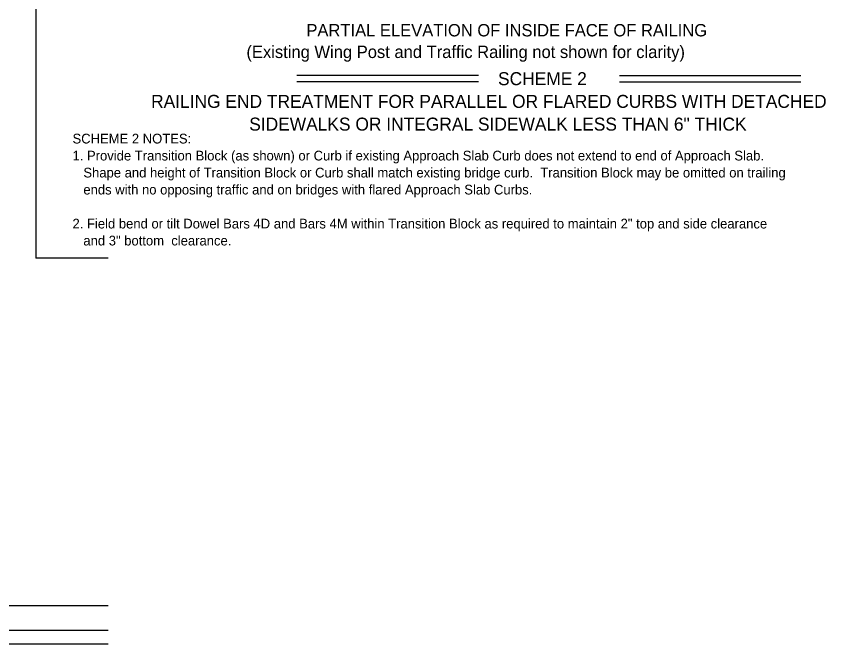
# Model space of a CAD drawing. Extents: x 21526.6 to 21598.7, y 56118.1 to 56155.9.
# Drawn here: x 21545.31 to 21562.06, y 56119.33 to 56132.33 of the extents above; entities that cross this region are included whole.
import ezdxf

# ---------------------------------------------------------------- set-up
doc = ezdxf.new("R2010")
doc.units = 0
doc.layers.add('Border', color=7, linetype='Continuous')
doc.layers.add('PlotBorder_dp', color=7, linetype='Continuous')

msp = doc.modelspace()

# ---------------------------------------------------------------- linework, layer by layer
at = {"layer": 'Border'}
for p, q in [((21547.212, 56120.12), (21526.6, 56120.12)), ((21547.212, 56119.605), (21526.6, 56119.605)), ((21526.6, 56119.332), (21547.212, 56119.332))]:
    msp.add_line(p, q, dxfattribs=at)
at = {"layer": 'PlotBorder_dp'}
for p, q in [((21545.716, 56153.256), (21545.716, 56127.317)), ((21554.877, 56131.105), (21551.118, 56131.105)), ((21557.792, 56131.105), (21561.551, 56131.105)), ((21554.877, 56130.972), (21551.118, 56130.972)), ((21557.792, 56130.972), (21561.551, 56130.972)), ((21547.212, 56127.317), (21545.716, 56127.317))]:
    msp.add_line(p, q, dxfattribs=at)

# ---------------------------------------------------------------- texts
for s, height, p in [('PARTIAL ELEVATION OF INSIDE FACE OF RAILING', 0.256, (21551.315, 56131.912)), ('(Existing Wing Post and Traffic Railing not shown for clarity)', 0.256, (21550.074, 56131.464)), ('SCHEME 2', 0.2688, (21555.281, 56130.902)), ('RAILING END TREATMENT FOR PARALLEL OR FLARED CURBS WITH DETACHED', 0.2688, (21548.101, 56130.432)), ('SIDEWALKS OR INTEGRAL SIDEWALK LESS THAN 6" THICK', 0.2688, (21550.132, 56129.961)), ('SCHEME 2 NOTES:', 0.2016, (21546.475, 56129.694)), ('1. Provide Transition Block (as shown) or Curb if existing Approach Slab Curb does not extend to end of Approach Slab.  ', 0.2016, (21546.475, 56129.342)), ('   Shape and height of Transition Block or Curb shall match existing bridge curb.  Transition Block may be omitted on trailing ', 0.2016, (21546.475, 56128.99)), ('   ends with no opposing traffic and on bridges with flared Approach Slab Curbs.', 0.2016, (21546.475, 56128.638)), ('2. Field bend or tilt Dowel Bars 4D and Bars 4M within Transition Block as required to maintain 2" top and side clearance ', 0.2016, (21546.475, 56127.934)), ('   and 3" bottom  clearance.', 0.2016, (21546.475, 56127.582))]:
    msp.add_text(s, height=height, dxfattribs=at).set_placement(p)

doc.saveas('drawing.dxf')
